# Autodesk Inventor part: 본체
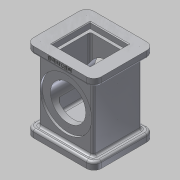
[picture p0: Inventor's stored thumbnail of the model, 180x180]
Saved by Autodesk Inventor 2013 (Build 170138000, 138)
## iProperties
Created: 2017-08
Part Number: 본체
Material: 알루미늄 6061
Document SubType Name: 모델링
Designer: Administrator
Density: 1 g/cm^3
Author: Administrator
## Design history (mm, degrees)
sketch "스케치5"
  geometry: L1 (-939.8, -838.2)-(939.8, -838.2); L2 (939.8, -838.2)-(939.8, 838.2); L3 (939.8, 838.2)-(-939.8, 838.2); L4 (-939.8, 838.2)-(-939.8, -838.2); L5 (-939.8, -838.2)-(939.8, 838.2); L6 (939.8, -838.2)-(-939.8, 838.2); 1 further point
  constraints: 12 end point, 2 midpoint, 2 parallel, 1 horizontal, 1 perpendicular
  dimensions: "d6" = 1879.6 distance of L2.end L3.end; "d8" = 1676.4 distance of L3.end L1.start
extrude "돌출1" new body sketch "스케치5" distance "d9" = 2743.2; taper "d10" = 0 deg
sketch "스케치8"
  geometry: L1 (939.8, -838.2)-(-939.8, -838.2) reference; L2 (939.8, 838.2)-(939.8, -838.2) reference; L3 (-939.8, 838.2)-(939.8, 838.2) reference; L4 (-939.8, -838.2)-(-939.8, 838.2) reference; L5 (-1168.4, -1041.4)-(1168.4, -1041.4); L6 (1168.4, -1041.4)-(1168.4, 1041.4); L7 (1168.4, 1041.4)-(-1168.4, 1041.4); L8 (-1168.4, 1041.4)-(-1168.4, -1041.4); L9 (-1168.4, -1041.4)-(1168.4, 1041.4); L10 (1168.4, -1041.4)-(-1168.4, 1041.4); 1 further point
  constraints: 12 end point, 2 midpoint, 2 parallel, 1 horizontal, 1 perpendicular
  dimensions: "d19" = 2336.8 distance of L6.end L7.end; "d21" = 2082.8 distance of L7.end L5.start
extrude "돌출3" join sketch "스케치8" distance "d22" = 254; taper "d23" = 0 deg
sketch "스케치9"
  geometry: L1 (-609.6, -609.6)-(609.6, -609.6); L2 (609.6, -609.6)-(609.6, 609.6); L3 (609.6, 609.6)-(-609.6, 609.6); L4 (-609.6, 609.6)-(-609.6, -609.6); L5 (-609.6, -609.6)-(609.6, 609.6); L6 (609.6, -609.6)-(-609.6, 609.6); 1 further point
  constraints: 12 end point, 2 midpoint, 2 parallel, 1 horizontal, 1 perpendicular
  dimensions: "d24" = 1219.2 distance of L2.end L3.end; "d26" = 1219.2 distance of L3.end L1.start
extrude "돌출4" cut sketch "스케치9" distance "d27" = 406.4; taper "d28" = 0 deg
sketch "스케치11"
  geometry: L1 (-1168.4, -1041.4)-(1168.4, -1041.4); L2 (1168.4, -1041.4)-(1168.4, 1041.4); L3 (1168.4, 1041.4)-(-1168.4, 1041.4); L4 (-1168.4, 1041.4)-(-1168.4, -1041.4); L5 (-1168.4, -1041.4)-(1168.4, 1041.4); L6 (1168.4, -1041.4)-(-1168.4, 1041.4); 1 further point
  constraints: 12 end point, 2 midpoint, 2 parallel, 1 horizontal, 1 perpendicular
  dimensions: "d34" = 2336.8 distance of L2.end L3.end; "d36" = 2082.8 distance of L3.end L1.start
extrude "돌출6" join sketch "스케치11" distance "d37" = 254; taper "d38" = 0 deg
fillet "모깎기1" dims "d72" = 254
sketch "스케치24"
  geometry: L1 (1854.2, -254)-(25.4, -254) reference; C1 r 889 at (939.8, 1117.6); 2 further points
  constraints: 1 centre point, 1 midpoint, 1 vertical alignment
  dimensions: "d76" = 1371.6 distance from line of L1 C1.centre; "d77" = 1778 diameter of C1
extrude "돌출14" cut sketch "스케치24" distance "d78" = 76.2; taper "d79" = 0 deg
sketch "스케치25"
  geometry: L1 (1854.2, -254)-(25.4, -254) reference; C1 r 889 at (939.8, 1117.6); 2 further points
  constraints: 1 centre point, 1 midpoint, 1 vertical alignment
  dimensions: "d80" = 1371.6 distance from line of L1 C1.centre; "d81" = 1778 diameter of C1
extrude "돌출15" cut sketch "스케치25" distance "d82" = 76.2; taper "d83" = 0 deg
sketch "스케치26"
  geometry: C1 r 889 at (0, 0) reference; C2 r 609.6 at (0, 0); 1 further point
  constraints: 1 centre point, 1 coincident
  dimensions: "d84" = 1219.2 diameter of C2
extrude "돌출16" cut sketch "스케치26" stored distance "d86" = 76.2; taper "d87" = 0 deg
sketch "스케치27"
  geometry: L1 (-660.4, -660.4)-(660.4, -660.4); L2 (660.4, -660.4)-(660.4, 660.4); L3 (660.4, 660.4)-(-660.4, 660.4); L4 (-660.4, 660.4)-(-660.4, -660.4); L5 (-660.4, -660.4)-(660.4, 660.4); L6 (660.4, -660.4)-(-660.4, 660.4); 1 further point
  constraints: 12 end point, 2 midpoint, 2 parallel, 1 horizontal, 1 perpendicular
  dimensions: "d88" = 1320.8 distance of L2.end L3.end; "d91" = 1320.8 distance of L3.end L1.start
extrude "돌출17" cut sketch "스케치27" distance "d92" = 203.2; taper "d93" = 0 deg
sketch "스케치28"
  geometry: L1 (-558.8, 558.8)-(558.8, 558.8); L2 (558.8, 558.8)-(558.8, -558.8); L3 (558.8, -558.8)-(-558.8, -558.8); L4 (-558.8, -558.8)-(-558.8, 558.8); L5 (-558.8, 558.8)-(558.8, -558.8); L6 (558.8, 558.8)-(-558.8, -558.8); 1 further point
  constraints: 12 end point, 2 midpoint, 2 parallel, 1 horizontal, 1 perpendicular
  dimensions: "d94" = 1117.6 distance of L1.start L1.end; "d96" = 1117.6 distance of L3.end L1.start
extrude "돌출18" cut sketch "스케치28" distance "d97" = 1879.6; taper "d98" = 0 deg
fillet "모깎기3" dims "d99" = 76.2
fillet "모깎기5" dims "d101" = 76.2
fillet "모깎기6" dims "d102" = 76.2
sketch "스케치34" dims "d103" = 1473.2
  geometry: C1 r 609.6 at (0, 0) reference; C2 r 889 at (0, 0) reference; 3 further points
  constraints: 2 horizontal alignment, 1 coincident, 2 other
hole "구멍1" sketch "스케치34" at (-736.6, 0) diameter "d105" = 3.2512; stored, may be unused: countersink angle "d109" = 82 deg, drill point angle "d111" = 118 deg; dims "d106" = 101.6, "d107" = 9.525, "d108" = 6.35, "d110" = 152.4
sketch "스케치35" dims "d112" = 1473.2
  geometry: C1 r 609.6 at (0, 0) reference; C2 r 889 at (0, 0) reference; 3 further points
  constraints: 2 vertical alignment, 1 coincident, 2 other
hole "구멍2" sketch "스케치35" at (0, 736.6) diameter "d114" = 3.2512; stored, may be unused: countersink angle "d118" = 82 deg, drill point angle "d120" = 118 deg; dims "d115" = 101.6, "d116" = 9.525, "d117" = 6.35, "d119" = 152.4
chamfer "모따기1" distance "d127" = 25.4; stored, may be unused: second distance "d128" = 3.175, angle "d129" = 45 deg
sketch "스케치36"
  geometry: L1 (-1524, 2082.8)-(0, 2082.8) reference; L2 (0, 0)-(-1524, 0) reference; L3 (-762, 2082.8)-(-762, 0); L4 (25.4, -330.2)-(-1549.4, -330.2) reference; 3 further points
  constraints: 2 end point, 2 midpoint, 2 point on line
  dimensions: "d130" = 965.2 distance from line of L4 point (-762, 635); "d131" = 1066.8 distance of point (-762, 635) point (-762, 1701.8)
hole "구멍3" sketch "스케치36" at (-762, 1701.8), (-762, 635) diameter "d132" = 4.1402; stored, may be unused: countersink angle "d136" = 82 deg, drill point angle "d138" = 118 deg; dims "d133" = 203.2, "d134" = 9.525, "d135" = 6.35, "d137" = 304.8
fillet "모깎기7" dims "d139" = 76.2
sketch "스케치38"
  geometry: A1 r 254 centre (914.4, 787.4) between (1168.4, 787.4) and (914.4, 1041.4) reference; A2 r 254 centre (-914.4, 787.4) between (-914.4, 1041.4) and (-1168.4, 787.4) reference; A3 r 254 centre (-914.4, -787.4) between (-1168.4, -787.4) and (-914.4, -1041.4) reference; A4 r 254 centre (914.4, -787.4) between (914.4, -1041.4) and (1168.4, -787.4) reference; 5 further points
  constraints: 4 coincident
hole "구멍5" sketch "스케치38" at (-914.4, 787.4), (914.4, 787.4), (914.4, -787.4), (-914.4, -787.4) diameter "d147" = 3.2512; stored, may be unused: countersink angle "d151" = 82 deg, drill point angle "d153" = 118 deg; dims "d148" = 101.6, "d149" = 9.525, "d150" = 6.35, "d152" = 152.4
node "작업 평면2"
sketch "스케치39"
  geometry: L1 (492.974, -15.199)-(1335.826, -15.199); L2 (1335.826, -15.199)-(1335.826, -137.201); L3 (1335.826, -137.201)-(492.974, -137.201); L4 (492.974, -137.201)-(492.974, -15.199); L5 (492.974, -76.2)-(1335.826, -76.2); L6 (914.4, -15.199)-(914.4, -137.201); L7 (1828.8, -177.8)-(0, -177.8) reference; L8 (0, -254)-(1828.8, -254) reference; L9 (-254, -177.8)-(0, -177.8) reference; L10 (-254, 0)-(-254, -177.8) reference; 1 further point
  constraints: 4 end point, 4 midpoint, 2 other
  dimensions: "d158" = 1168.4 distance between parallel lines of L10 L6; "d159" = 101.6 distance between parallel lines of L9 L5
extrude "돌출19" join sketch "스케치39" stored distance "d160" = 1879.6; taper "d161" = 0 deg
sketch "스케치40"
  geometry: A1 r 254 centre (-914.4, -787.4) between (-1168.4, -787.4) and (-914.4, -1041.4) reference; A2 r 254 centre (914.4, -787.4) between (914.4, -1041.4) and (1168.4, -787.4) reference; A3 r 254 centre (914.4, 787.4) between (1168.4, 787.4) and (914.4, 1041.4) reference; A4 r 254 centre (-914.4, 787.4) between (-914.4, 1041.4) and (-1168.4, 787.4) reference; 5 further points
  constraints: 4 coincident
hole "구멍6" sketch "스케치40" at (-914.4, 787.4), (914.4, 787.4), (914.4, -787.4), (-914.4, -787.4) diameter "d162" = 3.2512; stored, may be unused: countersink angle "d166" = 82 deg, drill point angle "d168" = 118 deg; dims "d163" = 101.6, "d164" = 9.525, "d165" = 6.35, "d167" = 152.4
node "솔리드1"
pattern_circular "원형 패턴1" dims angle "d122" = 360 deg
pattern_circular "원형 패턴2" dims angle "d125" = 360 deg
other parameters: "K계수" = 4.4, "BendRadius" = 3.048 (derived), "BendReliefWidth" = 3.048 (derived), "BendReliefDepth" = 1.524 (derived), "CornerReliefSize" = 12.192 (derived), "SeamGap" = 0.00508, "MinimumRemnant" = 6.096 (derived), "TransitionRadius" = 3.048 (= BendRadius), "d154" = 12.7
